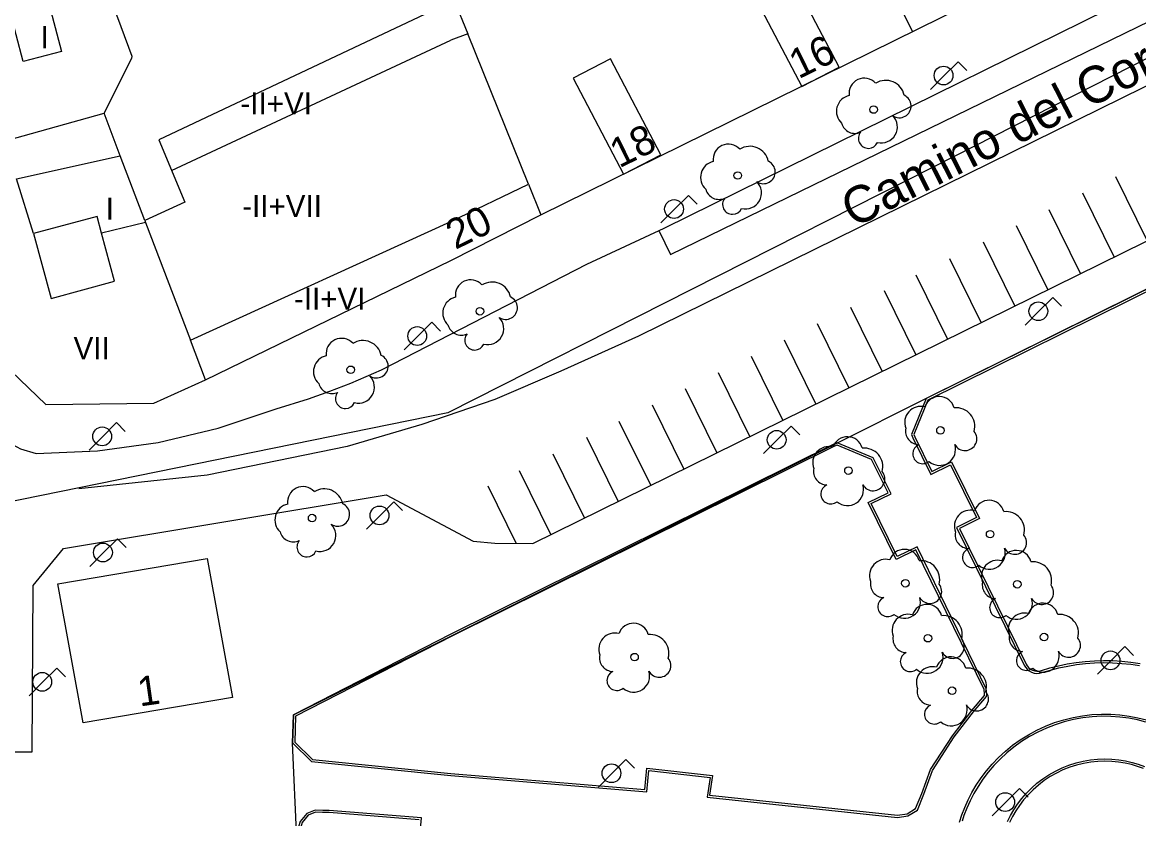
# Model space of a CAD drawing. Extents: x 282771 to 285132, y 4823109 to 4825496.
# Drawn here: x 282862 to 282937.8, y 4824094.8 to 4824148.8 of the extents above; entities that cross this region are included whole.
import ezdxf

# ---------------------------------------------------------------- set-up
doc = ezdxf.new("R2010")
doc.units = 0
for name, color, linetype in [('ACERA-BORDILLO', 7, 'Continuous'), ('APARCAMIENTO', 7, 'Continuous'), ('ARBOL', 7, 'Continuous'), ('BORDILLO', 7, 'Continuous'), ('CALLE-EJE', 7, 'Continuous'), ('CALLE-TEXTO', 7, 'Continuous'), ('EDIFICIO', 7, 'Continuous'), ('FAROLA', 7, 'Continuous'), ('INTERIOR-EDIFICIO', 7, 'Continuous'), ('MEDIANERA', 7, 'Continuous'), ('NUM-PORTAL', 7, 'Continuous'), ('PARQUE-JARDIN-AREA', 7, 'Continuous'), ('SENAL-VIARIA', 7, 'Continuous'), ('TXT-ALTURA-EDIFICIO', 7, 'Continuous'), ('ZONA-VERDE', 7, 'Continuous')]:
    doc.layers.add(name, color=color, linetype=linetype)

msp = doc.modelspace()

# ---------------------------------------------------------------- linework, layer by layer
at = {"layer": 'ACERA-BORDILLO'}
for points in [[(282846.561, 4824160.183), (282858.221, 4824124.893), (282858.611, 4824123.943), (282859.392, 4824122.047), (282860.058, 4824121.16), (282860.916, 4824120.417), (282861.912, 4824119.874), (282862.976, 4824119.56), (282867.122, 4824119.742), (282871.25, 4824120.311), (282875.308, 4824121.262), (282879.242, 4824122.581), (282881.441, 4824123.264), (282882.884, 4824123.773), (282884.306, 4824124.327), (282886.397, 4824125.234), (282900.321, 4824132.389), (282905.563, 4824134.831), (282989.18, 4824176.115)], [(282862.704, 4824099.31), (282862.769, 4824110.611), (282864.826, 4824113.101), (282886.708, 4824116.757), (282892.615, 4824113.616), (282894.093, 4824113.475), (282896.66, 4824113.44), (282970.559, 4824149.853)], [(282891.09, 4824031.424), (282865.031, 4824034.178), (282864.778, 4824034.216), (282864.522, 4824034.277), (282864.266, 4824034.363), (282864.014, 4824034.474), (282863.768, 4824034.61), (282863.534, 4824034.771), (282863.313, 4824034.956), (282863.111, 4824035.162), (282862.929, 4824035.386), (282862.77, 4824035.625), (282862.636, 4824035.876), (282862.527, 4824036.135), (282862.445, 4824036.399), (282862.388, 4824036.663), (282862.356, 4824036.924), (282862.346, 4824037.179), (282862.594, 4824080.223), (282861.132, 4824080.231), (282861.242, 4824099.318), (282862.704, 4824099.31)]]:
    msp.add_lwpolyline(points, dxfattribs=at)
at = {"layer": 'APARCAMIENTO'}
for points in [[(282936.177, 4824138.336), (282938.327, 4824133.971)], [(282933.94, 4824137.234), (282936.091, 4824132.869)], [(282931.668, 4824136.115), (282933.819, 4824131.749)], [(282929.438, 4824135.016), (282931.589, 4824130.651)], [(282927.206, 4824133.916), (282929.357, 4824129.551)], [(282924.919, 4824132.789), (282927.07, 4824128.424)], [(282922.643, 4824131.668), (282924.794, 4824127.302)], [(282920.491, 4824130.607), (282922.642, 4824126.242)], [(282918.216, 4824129.486), (282920.367, 4824125.121)], [(282915.952, 4824128.371), (282918.103, 4824124.006)], [(282913.707, 4824127.265), (282915.858, 4824122.899)], [(282911.472, 4824126.163), (282913.623, 4824121.798)], [(282909.224, 4824125.056), (282911.375, 4824120.69)], [(282906.996, 4824123.958), (282909.147, 4824119.593)], [(282904.76, 4824122.856), (282906.911, 4824118.491)], [(282902.503, 4824121.744), (282904.654, 4824117.379)], [(282900.305, 4824120.661), (282902.455, 4824116.295)], [(282898.014, 4824119.532), (282900.165, 4824115.167)], [(282895.735, 4824118.409), (282897.886, 4824114.044)], [(282893.602, 4824117.358), (282895.526, 4824113.456)]]:
    msp.add_lwpolyline(points, dxfattribs=at)
at = {"layer": 'ARBOL'}
for centre in [(282919.778, 4824142.886), (282910.561, 4824138.41), (282893.073, 4824129.203), (282884.306, 4824125.234), (282924.31, 4824121.123), (282918.07, 4824118.393), (282881.689, 4824115.175), (282927.68, 4824114.083), (282921.93, 4824110.753), (282929.52, 4824110.683), (282923.46, 4824107.023), (282931.34, 4824107.103), (282903.56, 4824105.743), (282925.1, 4824103.463)]:
    msp.add_circle(centre, 0.255, dxfattribs=at)
for centre, radius, start, end in [((282919.148, 4824143.98), 1.038, 42.38202, 188.12408), ((282920.607, 4824143.595), 1.272, 11.77247, 122.53899), ((282918.351, 4824142.761), 1.097, 102.17153, 227.29582), ((282921.525, 4824143.128), 0.797, 235.7022, 65.73076), ((282920.304, 4824141.707), 1.086, 255.69421, 44.66769), ((282918.51, 4824142.202), 0.935, 195.33871, 294.87209), ((282919.421, 4824140.926), 0.672, 140.47646, 336.21223), ((282909.931, 4824139.504), 1.038, 42.38202, 188.12408), ((282911.39, 4824139.119), 1.272, 11.77247, 122.53899), ((282912.308, 4824138.652), 0.797, 235.7022, 65.73076), ((282909.134, 4824138.285), 1.097, 102.17153, 227.29582), ((282911.087, 4824137.231), 1.086, 255.69421, 44.66769), ((282909.293, 4824137.726), 0.935, 195.33871, 294.87209), ((282910.204, 4824136.45), 0.672, 140.47646, 336.21223), ((282892.443, 4824130.297), 1.038, 42.38202, 188.12408), ((282893.903, 4824129.912), 1.272, 11.77247, 122.53899), ((282891.647, 4824129.078), 1.097, 102.17153, 227.29582), ((282894.821, 4824129.445), 0.797, 235.7022, 65.73076), ((282893.6, 4824128.024), 1.086, 255.69421, 44.66769), ((282891.805, 4824128.519), 0.935, 195.33871, 294.87209), ((282883.676, 4824126.328), 1.038, 42.38202, 188.12408), ((282892.717, 4824127.243), 0.672, 140.47646, 336.21223), ((282885.135, 4824125.943), 1.272, 11.77247, 122.53899), ((282882.879, 4824125.109), 1.097, 102.17153, 227.29582), ((282886.054, 4824125.477), 0.797, 235.7022, 65.73076), ((282883.038, 4824124.551), 0.935, 195.33871, 294.87209), ((282884.832, 4824124.055), 1.086, 255.69421, 44.66769), ((282883.949, 4824123.274), 0.672, 140.47646, 336.21223), ((282922.98, 4824121.653), 1.097, 75.4318, 200.55608), ((282924.24, 4824122.383), 1.038, 15.64228, 161.38435), ((282925.37, 4824121.383), 1.272, 345.03273, 95.79925), ((282922.87, 4824121.083), 0.935, 168.59898, 268.13236), ((282918, 4824119.653), 1.038, 15.64228, 161.38435), ((282925.98, 4824120.553), 0.797, 208.96247, 38.99103), ((282916.74, 4824118.923), 1.097, 75.4318, 200.55608), ((282919.13, 4824118.653), 1.272, 345.03273, 95.79925), ((282923.11, 4824119.533), 0.672, 113.73672, 309.4725), ((282924.25, 4824119.833), 1.086, 228.95447, 17.92796), ((282916.63, 4824118.353), 0.935, 168.59898, 268.13236), ((282919.74, 4824117.823), 0.797, 208.96247, 38.99103), ((282916.87, 4824116.803), 0.672, 113.73672, 309.4725), ((282918.01, 4824117.103), 1.086, 228.95447, 17.92796), ((282881.059, 4824116.268), 1.038, 42.38202, 188.12408), ((282882.518, 4824115.884), 1.272, 11.77247, 122.53899), ((282880.263, 4824115.049), 1.097, 102.17153, 227.29582), ((282883.437, 4824115.417), 0.797, 235.7022, 65.73076), ((282927.61, 4824115.343), 1.038, 15.64228, 161.38435), ((282926.35, 4824114.613), 1.097, 75.4318, 200.55608), ((282928.74, 4824114.343), 1.272, 345.03273, 95.79925), ((282882.216, 4824113.996), 1.086, 255.69421, 44.66769), ((282880.421, 4824114.491), 0.935, 195.33871, 294.87209), ((282881.333, 4824113.215), 0.672, 140.47646, 336.21223), ((282926.24, 4824114.043), 0.935, 168.59898, 268.13236), ((282929.35, 4824113.513), 0.797, 208.96247, 38.99103), ((282921.86, 4824112.013), 1.038, 15.64228, 161.38435), ((282926.48, 4824112.493), 0.672, 113.73672, 309.4725), ((282927.62, 4824112.793), 1.086, 228.95447, 17.92796), ((282929.45, 4824111.943), 1.038, 15.64228, 161.38435), ((282920.6, 4824111.283), 1.097, 75.4318, 200.55608), ((282922.99, 4824111.013), 1.272, 345.03273, 95.79925), ((282928.19, 4824111.213), 1.097, 75.4318, 200.55608), ((282930.58, 4824110.943), 1.272, 345.03273, 95.79925), ((282920.49, 4824110.713), 0.935, 168.59898, 268.13236), ((282923.6, 4824110.183), 0.797, 208.96247, 38.99103), ((282928.08, 4824110.643), 0.935, 168.59898, 268.13236), ((282931.19, 4824110.113), 0.797, 208.96247, 38.99103), ((282920.73, 4824109.163), 0.672, 113.73672, 309.4725), ((282921.87, 4824109.463), 1.086, 228.95447, 17.92796), ((282923.39, 4824108.283), 1.038, 15.64228, 161.38435), ((282928.32, 4824109.093), 0.672, 113.73672, 309.4725), ((282929.46, 4824109.393), 1.086, 228.95447, 17.92796), ((282931.27, 4824108.363), 1.038, 15.64228, 161.38435), ((282922.13, 4824107.553), 1.097, 75.4318, 200.55608), ((282924.52, 4824107.283), 1.272, 345.03273, 95.79925), ((282930.01, 4824107.633), 1.097, 75.4318, 200.55608), ((282932.4, 4824107.363), 1.272, 345.03273, 95.79925), ((282903.49, 4824107.003), 1.038, 15.64228, 161.38435), ((282902.23, 4824106.273), 1.097, 75.4318, 200.55608), ((282904.62, 4824106.003), 1.272, 345.03273, 95.79925), ((282922.02, 4824106.983), 0.935, 168.59898, 268.13236), ((282925.13, 4824106.453), 0.797, 208.96247, 38.99103), ((282929.9, 4824107.063), 0.935, 168.59898, 268.13236), ((282933.01, 4824106.533), 0.797, 208.96247, 38.99103), ((282922.26, 4824105.433), 0.672, 113.73672, 309.4725), ((282923.4, 4824105.733), 1.086, 228.95447, 17.92796), ((282930.14, 4824105.513), 0.672, 113.73672, 309.4725), ((282931.28, 4824105.813), 1.086, 228.95447, 17.92796), ((282902.12, 4824105.703), 0.935, 168.59898, 268.13236), ((282905.23, 4824105.173), 0.797, 208.96247, 38.99103), ((282925.03, 4824104.723), 1.038, 15.64228, 161.38435), ((282902.36, 4824104.153), 0.672, 113.73672, 309.4725), ((282903.5, 4824104.453), 1.086, 228.95447, 17.92796), ((282923.77, 4824103.993), 1.097, 75.4318, 200.55608), ((282926.16, 4824103.723), 1.272, 345.03273, 95.79925), ((282923.66, 4824103.423), 0.935, 168.59898, 268.13236), ((282926.77, 4824102.893), 0.797, 208.96247, 38.99103), ((282923.9, 4824101.873), 0.672, 113.73672, 309.4725), ((282925.04, 4824102.173), 1.086, 228.95447, 17.92796)]:
    msp.add_arc(centre, radius, start, end, dxfattribs=at)
at = {"layer": 'BORDILLO'}
for points in [[(282971.078, 4824146.91), (282923.339, 4824123.291), (282922.34, 4824120.841), (282922.43, 4824120.623), (282923.65, 4824118.133), (282925, 4824118.793), (282926.76, 4824115.203), (282925.41, 4824114.543), (282929.986, 4824105.199), (282930.073, 4824105.054), (282930.188, 4824104.921), (282930.331, 4824104.806), (282930.494, 4824104.718), (282930.672, 4824104.662), (282930.853, 4824104.639), (282931.03, 4824104.65), (282931.194, 4824104.688)], [(282891.09, 4824107.293), (282880.422, 4824101.837), (282880.369, 4824099.917), (282881.653, 4824098.659), (282891.09, 4824097.703), (282904.392, 4824096.594), (282904.53, 4824098.04), (282908.682, 4824097.581), (282908.476, 4824096.25), (282921.392, 4824094.863), (282922.103, 4824094.978), (282922.745, 4824095.368), (282923.181, 4824096.447), (282923.778, 4824098.053), (282925.246, 4824100.326), (282926.554, 4824102.024), (282927.431, 4824103.078), (282927.457, 4824103.254), (282927.415, 4824103.595), (282922.72, 4824113.223), (282921.37, 4824112.563), (282919.61, 4824116.153), (282920.96, 4824116.813), (282919.754, 4824119.267), (282917.31, 4824120.279), (282917.07, 4824120.183), (282891.09, 4824107.293)], [(282931.194, 4824104.688), (282931.766, 4824104.861), (282932.35, 4824105.01), (282932.943, 4824105.134), (282933.544, 4824105.232), (282934.151, 4824105.303), (282934.762, 4824105.348), (282935.376, 4824105.366), (282935.991, 4824105.356), (282936.604, 4824105.319), (282937.215, 4824105.254), (282937.821, 4824105.163)], [(282925.601, 4824094.546), (282925.766, 4824095.047), (282925.961, 4824095.55), (282926.187, 4824096.054), (282926.447, 4824096.556), (282926.74, 4824097.054), (282927.067, 4824097.543), (282927.428, 4824098.022), (282927.824, 4824098.486), (282928.252, 4824098.933), (282928.714, 4824099.358), (282929.206, 4824099.76), (282929.727, 4824100.133), (282930.275, 4824100.476), (282930.847, 4824100.786), (282931.439, 4824101.06), (282932.049, 4824101.296), (282932.673, 4824101.494), (282933.306, 4824101.651), (282933.946, 4824101.767), (282934.588, 4824101.842), (282935.228, 4824101.876), (282935.863, 4824101.871), (282936.489, 4824101.828), (282937.103, 4824101.748), (282937.702, 4824101.633), (282938.284, 4824101.486)], [(282938.085, 4824098.182), (282937.685, 4824098.328), (282937.268, 4824098.451), (282936.834, 4824098.55), (282936.386, 4824098.624), (282935.926, 4824098.669), (282935.456, 4824098.684), (282934.98, 4824098.667), (282934.501, 4824098.618), (282934.022, 4824098.536), (282933.546, 4824098.42), (282933.077, 4824098.271), (282932.618, 4824098.089), (282932.173, 4824097.876), (282931.745, 4824097.633), (282931.337, 4824097.362), (282930.951, 4824097.066), (282930.589, 4824096.747), (282930.254, 4824096.409), (282929.946, 4824096.054), (282929.667, 4824095.686), (282929.417, 4824095.307), (282929.195, 4824094.921), (282929.002, 4824094.531)], [(282888.082, 4824083.938), (282889.113, 4824094.841), (282882.85, 4824095.343), (282882.408, 4824095.342), (282881.892, 4824095.369), (282881.341, 4824095.14), (282880.883, 4824094.589), (282880.699, 4824094.015), (282880.648, 4824093.367), (282880.64, 4824090.933), (282878.762, 4824090.447), (282877.969, 4824089.333), (282877.349, 4824088.323), (282876.93, 4824087.243), (282876.92, 4824084.993)]]:
    msp.add_lwpolyline(points, dxfattribs=at)
at = {"layer": 'CALLE-EJE'}
msp.add_lwpolyline([(282994.379, 4824174.892), (282923.952, 4824139.042), (282890.9, 4824122.317), (282859.311, 4824115.893)], dxfattribs=at)
at = {"layer": 'EDIFICIO'}
for points in [[(282852.951, 4824149.202), (282856.161, 4824139.453), (282857.641, 4824134.943), (282860.681, 4824125.713), (282863.631, 4824122.873), (282870.961, 4824122.973), (282874.45, 4824124.553), (282891.09, 4824132.643), (282897.2, 4824135.743), (282946.78, 4824160.202)], [(282866.171, 4824101.283), (282864.431, 4824110.713), (282874.56, 4824112.433), (282876.3, 4824103.013), (282866.171, 4824101.283)]]:
    msp.add_lwpolyline(points, dxfattribs=at)
at = {"layer": 'FAROLA'}
for p, q in [((282925.502, 4824146.122), (282924.562, 4824145.192)), ((282926.092, 4824145.532), (282925.502, 4824146.122)), ((282924.562, 4824145.192), (282923.632, 4824144.252)), ((282907.218, 4824137.066), (282906.278, 4824136.136)), ((282907.808, 4824136.476), (282907.218, 4824137.066)), ((282906.278, 4824136.136), (282905.348, 4824135.196)), ((282931.929, 4824130.133), (282930.989, 4824129.203)), ((282932.519, 4824129.543), (282931.929, 4824130.133)), ((282930.989, 4824129.203), (282930.059, 4824128.263)), ((282889.801, 4824128.453), (282888.861, 4824127.523)), ((282890.391, 4824127.863), (282889.801, 4824128.453)), ((282888.861, 4824127.523), (282887.931, 4824126.583)), ((282868.427, 4824121.647), (282867.487, 4824120.717)), ((282869.017, 4824121.057), (282868.427, 4824121.647)), ((282914.18, 4824121.414), (282913.24, 4824120.484)), ((282914.77, 4824120.824), (282914.18, 4824121.414)), ((282867.487, 4824120.717), (282866.557, 4824119.777)), ((282913.24, 4824120.484), (282912.31, 4824119.544)), ((282887.239, 4824116.284), (282886.299, 4824115.354)), ((282887.829, 4824115.694), (282887.239, 4824116.284)), ((282886.299, 4824115.354), (282885.369, 4824114.414)), ((282868.483, 4824113.767), (282867.543, 4824112.837)), ((282869.073, 4824113.177), (282868.483, 4824113.767)), ((282867.543, 4824112.837), (282866.613, 4824111.897)), ((282936.824, 4824106.453), (282935.884, 4824105.523)), ((282937.414, 4824105.863), (282936.824, 4824106.453)), ((282935.884, 4824105.523), (282934.954, 4824104.583)), ((282864.365, 4824104.995), (282863.425, 4824104.065)), ((282864.955, 4824104.405), (282864.365, 4824104.995)), ((282863.425, 4824104.065), (282862.495, 4824103.125)), ((282902.975, 4824098.793), (282902.035, 4824097.863)), ((282903.565, 4824098.203), (282902.975, 4824098.793)), ((282902.035, 4824097.863), (282901.105, 4824096.923)), ((282929.68, 4824096.838), (282928.74, 4824095.908)), ((282930.27, 4824096.248), (282929.68, 4824096.838)), ((282928.74, 4824095.908), (282927.81, 4824094.968))]:
    msp.add_line(p, q, dxfattribs=at)
for centre in [(282924.522, 4824145.192), (282906.238, 4824136.136), (282930.949, 4824129.203), (282888.821, 4824127.523), (282867.447, 4824120.717), (282913.2, 4824120.484), (282886.259, 4824115.354), (282867.503, 4824112.837), (282935.844, 4824105.523), (282863.385, 4824104.065), (282901.995, 4824097.863), (282928.7, 4824095.908)]:
    msp.add_circle(centre, 0.637, dxfattribs=at)
at = {"layer": 'INTERIOR-EDIFICIO'}
for points in [[(282871.288, 4824140.837), (282873.06, 4824136.603), (282870.343, 4824135.368), (282870.397, 4824135.225), (282867.406, 4824134.494), (282867.101, 4824135.633), (282862.791, 4824134.473), (282861.631, 4824138.183), (282868.68, 4824139.746), (282867.581, 4824142.643), (282869.451, 4824146.372), (282869.491, 4824146.492), (282865.921, 4824156.142), (282869.112, 4824158.081), (282866.851, 4824162.762), (282869.331, 4824163.942), (282871.53, 4824159.552), (282875.328, 4824161.498), (282878.05, 4824162.892), (282884.56, 4824166.222), (282885.001, 4824165.273), (282891.09, 4824168.512)], [(282862.101, 4824146.152), (282861.151, 4824149.752), (282863.741, 4824150.432), (282864.681, 4824146.832), (282862.101, 4824146.152)], [(282891.324, 4824150.283), (282871.288, 4824140.837)]]:
    msp.add_lwpolyline(points, dxfattribs=at)
at = {"layer": 'MEDIANERA'}
for points in [[(282922.41, 4824148.172), (282914.99, 4824163.092), (282911.589, 4824169.484)], [(282911.5, 4824150.952), (282914.91, 4824144.443), (282917.44, 4824145.763), (282914.02, 4824152.272), (282911.5, 4824150.952)], [(282891.324, 4824150.283), (282892.26, 4824148.032)], [(282892.26, 4824148.032), (282891.09, 4824147.592)], [(282896.37, 4824137.813), (282892.26, 4824148.032)], [(282872.16, 4824138.753), (282891.09, 4824147.592)], [(282899.4, 4824145.003), (282902.81, 4824138.493), (282905.34, 4824139.813), (282901.92, 4824146.323), (282899.4, 4824145.003)], [(282856.161, 4824139.453), (282867.581, 4824142.643)], [(282870.343, 4824135.368), (282868.68, 4824139.746)], [(282891.09, 4824135.293), (282896.37, 4824137.813)], [(282896.37, 4824137.813), (282897.2, 4824135.743)], [(282870.343, 4824135.368), (282870.397, 4824135.225), (282873.431, 4824127.237)], [(282873.431, 4824127.237), (282891.09, 4824135.293)], [(282862.791, 4824134.473), (282863.981, 4824130.073), (282868.281, 4824131.233), (282867.406, 4824134.494)], [(282874.45, 4824124.553), (282873.431, 4824127.237)]]:
    msp.add_lwpolyline(points, dxfattribs=at)
at = {"layer": 'PARQUE-JARDIN-AREA'}
msp.add_lwpolyline([(282957.565, 4824026.52), (282900.429, 4824032.546), (282893.142, 4824033.318), (282898.242, 4824082.861), (282876.902, 4824084.978), (282876.912, 4824087.228), (282877.349, 4824088.323), (282877.969, 4824089.333), (282878.744, 4824090.432), (282880.622, 4824090.919), (282880.648, 4824093.367), (282880.369, 4824099.917), (282880.422, 4824101.837), (282917.293, 4824120.266), (282923.323, 4824123.277), (282968.997, 4824145.941)], dxfattribs=at)
at = {"layer": 'SENAL-VIARIA'}
for points in [[(282966.366, 4824158.322), (282903.829, 4824127.512), (282898.57, 4824125.142), (282894.073, 4824123.214), (282889.134, 4824121.527), (282884.075, 4824120.04), (282874.582, 4824118.082), (282865.87, 4824117.158)], [(282905.231, 4824134.636), (282906.005, 4824133.062), (282948.232, 4824153.646), (282947.341, 4824155.456)]]:
    msp.add_lwpolyline(points, dxfattribs=at)
at = {"layer": 'ZONA-VERDE'}
for points in [[(282971.134, 4824146.77), (282923.457, 4824123.182), (282922.502, 4824120.841), (282922.567, 4824120.684), (282923.719, 4824118.333), (282925.069, 4824118.993), (282926.961, 4824115.134), (282925.611, 4824114.474), (282930.118, 4824105.271), (282930.195, 4824105.143), (282930.293, 4824105.029), (282930.414, 4824104.931), (282930.553, 4824104.857), (282930.704, 4824104.809), (282930.858, 4824104.79), (282931.008, 4824104.799), (282931.155, 4824104.833), (282931.726, 4824105.005)], [(282891.103, 4824097.852), (282904.257, 4824096.756), (282904.395, 4824098.206), (282908.855, 4824097.713), (282908.648, 4824096.382), (282921.388, 4824095.014), (282922.05, 4824095.121), (282922.625, 4824095.47), (282923.041, 4824096.501), (282923.643, 4824098.121), (282925.123, 4824100.412), (282926.437, 4824102.118), (282927.289, 4824103.142), (282927.305, 4824103.256), (282927.27, 4824103.552), (282922.651, 4824113.022), (282921.301, 4824112.362), (282919.409, 4824116.222), (282920.759, 4824116.882), (282919.644, 4824119.15), (282917.309, 4824120.117), (282917.132, 4824120.046), (282891.159, 4824107.159)], [(282891.159, 4824107.159), (282880.57, 4824101.744), (282880.521, 4824099.978), (282881.721, 4824098.803), (282891.103, 4824097.852)], [(282931.726, 4824105.005), (282932.316, 4824105.156), (282932.916, 4824105.281), (282933.523, 4824105.38), (282934.136, 4824105.453), (282934.754, 4824105.498), (282935.375, 4824105.516), (282935.996, 4824105.506), (282936.617, 4824105.468), (282937.234, 4824105.403), (282937.847, 4824105.311)], [(282938.243, 4824101.341), (282937.67, 4824101.486), (282937.08, 4824101.6), (282936.474, 4824101.679), (282935.858, 4824101.721), (282935.232, 4824101.726), (282934.601, 4824101.692), (282933.968, 4824101.618), (282933.338, 4824101.504), (282932.713, 4824101.349), (282932.099, 4824101.155), (282931.498, 4824100.922), (282930.914, 4824100.652), (282930.35, 4824100.347), (282929.811, 4824100.009), (282929.297, 4824099.64), (282928.812, 4824099.245), (282928.358, 4824098.826), (282927.935, 4824098.386), (282927.545, 4824097.928), (282927.189, 4824097.456), (282926.867, 4824096.974), (282926.578, 4824096.484), (282926.323, 4824095.989), (282926.099, 4824095.492), (282925.907, 4824094.996), (282925.779, 4824094.606)], [(282928.866, 4824094.593), (282929.063, 4824094.992), (282929.289, 4824095.386), (282929.545, 4824095.773), (282929.83, 4824096.149), (282930.144, 4824096.511), (282930.486, 4824096.857), (282930.856, 4824097.182), (282931.25, 4824097.484), (282931.667, 4824097.76), (282932.104, 4824098.009), (282932.558, 4824098.226), (282933.026, 4824098.412), (282933.505, 4824098.564), (282933.991, 4824098.683), (282934.481, 4824098.767), (282934.97, 4824098.817), (282935.456, 4824098.834), (282935.935, 4824098.818), (282936.405, 4824098.773), (282936.863, 4824098.698), (282937.306, 4824098.596), (282937.732, 4824098.47), (282938.141, 4824098.322)], [(282888.949, 4824094.704), (282882.845, 4824095.193), (282882.404, 4824095.192), (282881.918, 4824095.218), (282881.433, 4824095.015), (282881.017, 4824094.515), (282880.847, 4824093.986), (282880.798, 4824093.361), (282880.79, 4824090.817), (282878.852, 4824090.315), (282878.094, 4824089.25), (282877.484, 4824088.256), (282877.08, 4824087.215), (282877.071, 4824085.13)]]:
    msp.add_lwpolyline(points, dxfattribs=at)

# ---------------------------------------------------------------- texts
at = {"layer": 'CALLE-TEXTO'}
msp.add_text('Camino del Cortijo', height=2.5, rotation=26.97803, dxfattribs=at).set_placement((282918.415, 4824134.821))
at = {"layer": 'NUM-PORTAL'}
for s, rotation, p in [('16', 26.11004, (282914.686, 4824144.929)), ('18', 26.11004, (282902.523, 4824138.886)), ('20', 26.14477, (282891.403, 4824133.357)), ('1', 8.20968, (282869.994, 4824102.388))]:
    msp.add_text(s, height=2, rotation=rotation, dxfattribs=at).set_placement(p)
at = {"layer": 'TXT-ALTURA-EDIFICIO'}
for s, p in [('I', (282863.269, 4824147.042)), ('-II+VI', (282876.828, 4824142.553)), ('I', (282867.689, 4824135.413)), ('-II+VII', (282876.948, 4824135.593)), ('-II+VI', (282880.458, 4824129.303)), ('VII', (282865.511, 4824125.953))]:
    msp.add_text(s, height=1.5, rotation=0.00004, dxfattribs=at).set_placement(p)

doc.saveas('drawing.dxf')
